// Mitsubishi GX Works2 project: 34.变址（10种产品3种型号）   PLC: FX3U/FX3UC

PROGRAM MAIN
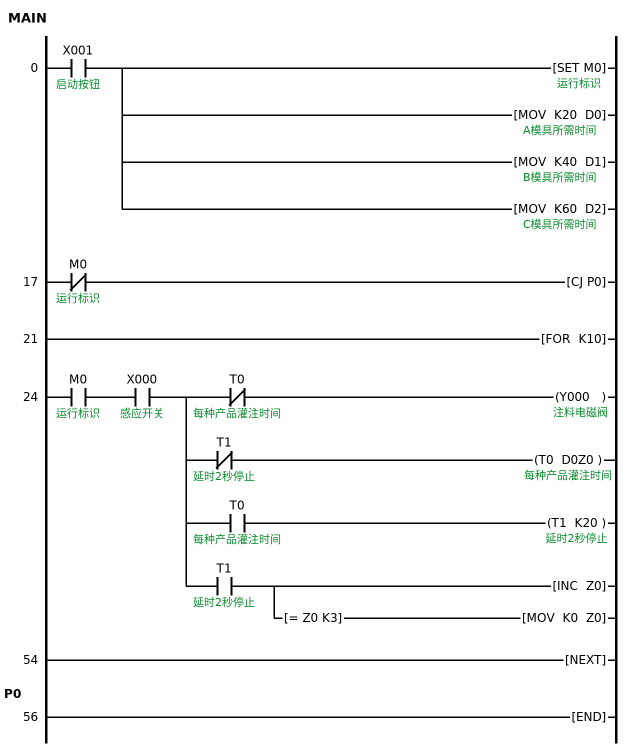
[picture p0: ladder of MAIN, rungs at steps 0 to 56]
0     LD      X001  ; 启动按钮
      SET     M0  ; 运行标识
      MOV     K20 D0  ; A模具所需时间
      MOV     K40 D1  ; B模具所需时间
      MOV     K60 D2  ; C模具所需时间
17    LDI     M0  ; 运行标识
      CJ      P0
        [note] 未启动时不循环
21    FOR     K10
        [note] 循环10次
24    LD      M0  ; 运行标识
      AND     X000  ; 感应开关
      MPS
      ANI     T0  ; 每种产品灌注时间
      OUT     Y000  ; 注料电磁阀
      MRD
      ANI     T1  ; 延时2秒停止
      OUT     T0 D0Z0  ; 每种产品灌注时间
      MRD
      AND     T0  ; 每种产品灌注时间
      OUT     T1 K20  ; 延时2秒停止
      MPP
      AND     T1  ; 延时2秒停止
      INC     Z0
        [note] Z0自加一
      AND=    Z0 K3
      MOV     K0 Z0
        [note] 3种产品灌注完循环进行
54    NEXT
      P0
56    END
END_PROGRAM
